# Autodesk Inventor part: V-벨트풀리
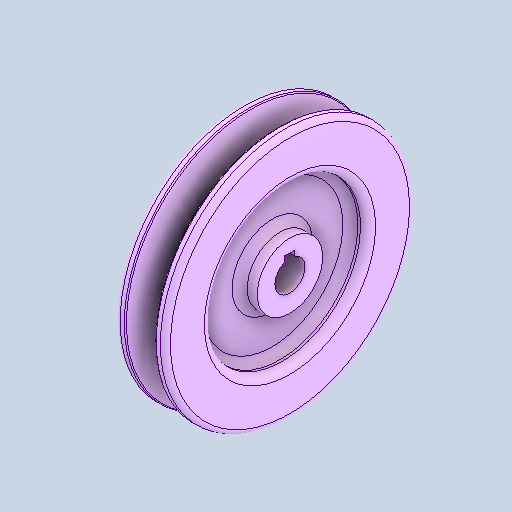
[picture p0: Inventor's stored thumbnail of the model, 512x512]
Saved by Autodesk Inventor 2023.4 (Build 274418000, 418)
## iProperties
Created: 2024-04
Part Number: V-벨트풀리
Material: 강철, 주조
Document SubType Name: Modeling
Designer: Edu03
Density: 7.85 g/cm^3
Appearance: 기본값
Author: jhkim
Sending System: Autodesk Inventor 2025
Preprocessor: ST-DEVELOPER v20
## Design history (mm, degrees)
feature "솔리드1"
node "솔리드2"
